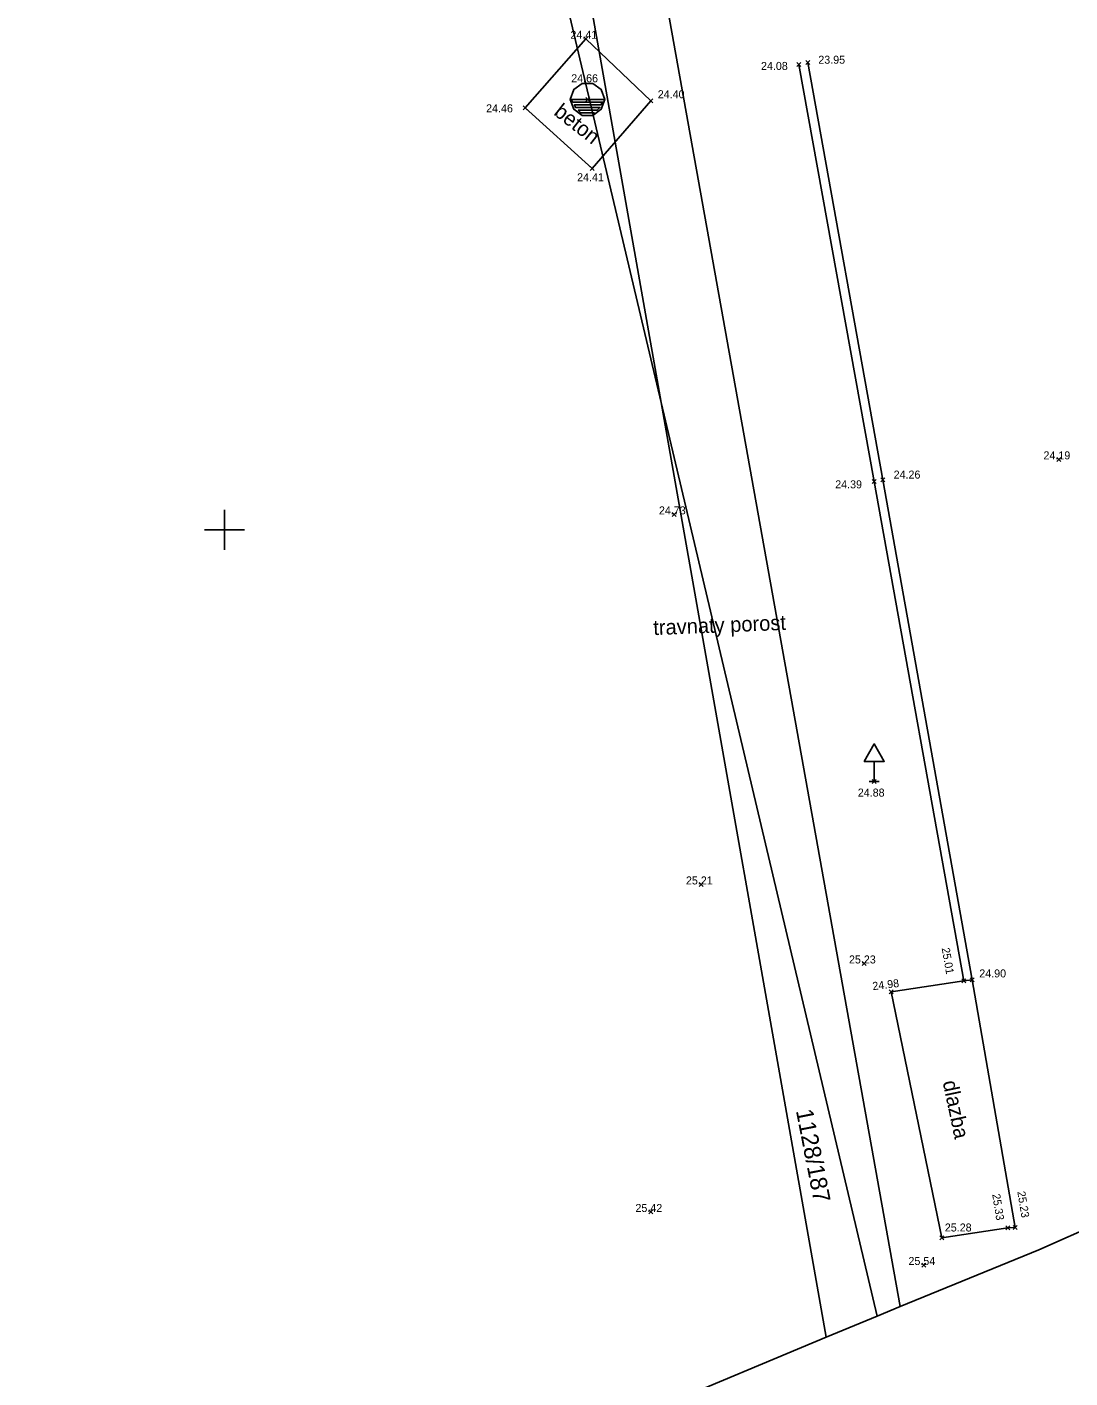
# Model space of a CAD drawing. Extents: x -772300 to -772183, y -1034101 to -1034019.
# Drawn here: x -772278.95 to -772258.1, y -1034066.96 to -1034039.94 of the extents above; entities that cross this region are included whole.
import ezdxf

# ---------------------------------------------------------------- set-up
doc = ezdxf.new("R2010")
doc.units = 0
for name, color, linetype in [('body', 7, 'Continuous'), ('dopravni_znacky', 7, 'Continuous'), ('elektricke_vedeni', 7, 'Continuous'), ('KM_hranice', 7, 'Continuous'), ('KM_popis', 7, 'Continuous'), ('mistni_popis', 7, 'Continuous'), ('oddeleni_ploch', 7, 'Continuous'), ('souradnicova_sit', 7, 'Continuous'), ('vyskove_koty', 7, 'Continuous')]:
    doc.layers.add(name, color=color, linetype=linetype)

msp = doc.modelspace()

# ---------------------------------------------------------------- linework, layer by layer
at = {"layer": 'body'}
for p, q in [((-772267.74, -1034040.22), (-772267.82, -1034040.14)), ((-772267.82, -1034040.22), (-772267.74, -1034040.14)), ((-772263.48, -1034040.73), (-772263.56, -1034040.65)), ((-772263.56, -1034040.73), (-772263.48, -1034040.65)), ((-772263.3, -1034040.69), (-772263.38, -1034040.61)), ((-772263.38, -1034040.69), (-772263.3, -1034040.61)), ((-772268.95, -1034041.6), (-772269.03, -1034041.52)), ((-772269.03, -1034041.6), (-772268.95, -1034041.52)), ((-772267.7, -1034041.43), (-772267.78, -1034041.35)), ((-772267.78, -1034041.43), (-772267.7, -1034041.35)), ((-772266.44, -1034041.46), (-772266.52, -1034041.38)), ((-772266.52, -1034041.46), (-772266.44, -1034041.38)), ((-772267.61, -1034042.81), (-772267.69, -1034042.73)), ((-772267.69, -1034042.81), (-772267.61, -1034042.73)), ((-772258.28, -1034048.63), (-772258.36, -1034048.55)), ((-772258.36, -1034048.63), (-772258.28, -1034048.55)), ((-772261.97, -1034049.07), (-772262.05, -1034048.99)), ((-772262.05, -1034049.07), (-772261.97, -1034048.99)), ((-772261.8, -1034049.04), (-772261.88, -1034048.96)), ((-772261.88, -1034049.04), (-772261.8, -1034048.96)), ((-772265.97, -1034049.73), (-772266.05, -1034049.65)), ((-772266.05, -1034049.73), (-772265.97, -1034049.65)), ((-772261.97, -1034055.07), (-772262.05, -1034054.99)), ((-772262.05, -1034055.07), (-772261.97, -1034054.99)), ((-772265.43, -1034057.13), (-772265.51, -1034057.05)), ((-772265.51, -1034057.13), (-772265.43, -1034057.05)), ((-772262.17, -1034058.71), (-772262.25, -1034058.63)), ((-772262.25, -1034058.71), (-772262.17, -1034058.63)), ((-772260.18, -1034059.06), (-772260.26, -1034058.98)), ((-772260.26, -1034059.06), (-772260.18, -1034058.98)), ((-772260.01, -1034059.04), (-772260.09, -1034058.96)), ((-772260.09, -1034059.04), (-772260.01, -1034058.96)), ((-772261.63, -1034059.28), (-772261.71, -1034059.2)), ((-772261.71, -1034059.28), (-772261.63, -1034059.2)), ((-772266.44, -1034063.68), (-772266.52, -1034063.6)), ((-772266.52, -1034063.68), (-772266.44, -1034063.6)), ((-772259.3, -1034064), (-772259.38, -1034063.92)), ((-772259.38, -1034064), (-772259.3, -1034063.92)), ((-772259.15, -1034063.99), (-772259.23, -1034063.91)), ((-772259.23, -1034063.99), (-772259.15, -1034063.91)), ((-772260.62, -1034064.2), (-772260.7, -1034064.12)), ((-772260.7, -1034064.2), (-772260.62, -1034064.12)), ((-772260.98, -1034064.74), (-772261.06, -1034064.66)), ((-772261.06, -1034064.74), (-772260.98, -1034064.66))]:
    msp.add_line(p, q, dxfattribs=at)
at = {"layer": 'dopravni_znacky'}
msp.add_line((-772262.11, -1034055.03), (-772261.91, -1034055.03), dxfattribs=at)
msp.add_lwpolyline([(-772262.01, -1034055.03), (-772262.01, -1034054.63), (-772261.81, -1034054.63), (-772262.01, -1034054.28), (-772262.21, -1034054.63), (-772262.01, -1034054.63)], dxfattribs=at)
at = {"layer": 'elektricke_vedeni'}
msp.add_lwpolyline([(-772267.4, -1034041.39), (-772267.468, -1034041.587), (-772267.638, -1034041.71), (-772267.849, -1034041.71), (-772268.019, -1034041.587), (-772268.087, -1034041.39), (-772268.019, -1034041.193), (-772267.849, -1034041.07), (-772267.638, -1034041.07), (-772267.468, -1034041.193), (-772267.4, -1034041.39), (-772268.08, -1034041.39), (-772268.039, -1034041.444), (-772267.441, -1034041.444), (-772267.475, -1034041.499), (-772268.005, -1034041.499), (-772267.985, -1034041.553), (-772267.495, -1034041.553), (-772267.55, -1034041.608), (-772267.93, -1034041.608), (-772267.876, -1034041.662), (-772267.604, -1034041.662)], dxfattribs=at)
at = {"layer": 'KM_hranice'}
for p, q in [((-772273.024, -1034018.905), (-772266.27, -1034047.45)), ((-772271.316, -1034018.905), (-772266.27, -1034047.45)), ((-772261.49, -1034065.53), (-772269.849, -1034018.905)), ((-772266.27, -1034047.45), (-772262.97, -1034066.14)), ((-772266.27, -1034047.45), (-772261.95, -1034065.72)), ((-772250.49, -1034060.71), (-772258.72, -1034064.4)), ((-772258.72, -1034064.4), (-772261.49, -1034065.53)), ((-772261.49, -1034065.53), (-772261.95, -1034065.72)), ((-772261.95, -1034065.72), (-772262.97, -1034066.14)), ((-772262.97, -1034066.14), (-772287.27, -1034076.31))]:
    msp.add_line(p, q, dxfattribs=at)
at = {"layer": 'oddeleni_ploch'}
msp.add_line((-772260.05, -1034059), (-772259.19, -1034063.95), dxfattribs=at)
msp.add_lwpolyline([(-772266.48, -1034041.42), (-772267.78, -1034040.18), (-772268.99, -1034041.56), (-772267.65, -1034042.77)], close=True, dxfattribs=at)
for points in [[(-772263.52, -1034040.69), (-772262.01, -1034049.03), (-772260.22, -1034059.02), (-772261.67, -1034059.24), (-772260.66, -1034064.16), (-772259.34, -1034063.96), (-772259.19, -1034063.95)], [(-772263.34, -1034040.65), (-772261.84, -1034049), (-772260.05, -1034059), (-772260.22, -1034059.02)]]:
    msp.add_lwpolyline(points, dxfattribs=at)
at = {"layer": 'souradnicova_sit'}
for p, q in [((-772275, -1034049.6), (-772275, -1034050.4)), ((-772275.4, -1034050), (-772274.6, -1034050))]:
    msp.add_line(p, q, dxfattribs=at)

# ---------------------------------------------------------------- texts
at = {"layer": 'KM_popis'}
msp.add_text('1128/187', height=0.34, rotation=281.0931, dxfattribs=at).set_placement((-772263.577, -1034061.614))
at = {"layer": 'mistni_popis'}
for s, rotation, p in [('beton', 321.945, (-772268.437, -1034041.686)), ('travnaty porost', 2.2918, (-772266.422, -1034052.105)), ('dlazba', 281.8952, (-772260.642, -1034061.04))]:
    msp.add_text(s, height=0.3, rotation=rotation, dxfattribs=at).set_placement(p)
at = {"layer": 'vyskove_koty'}
for s, p in [('24.41', (-772268.085, -1034040.18)), ('24.08', (-772264.274, -1034040.802)), ('23.95', (-772263.128, -1034040.678)), ('24.66', (-772268.069, -1034041.049)), ('24.40', (-772266.338, -1034041.368)), ('24.46', (-772269.771, -1034041.65)), ('24.41', (-772267.951, -1034043.028)), ('24.19', (-772258.625, -1034048.59)), ('24.26', (-772261.622, -1034048.974)), ('24.39', (-772262.79, -1034049.169)), ('24.73', (-772266.315, -1034049.69)), ('24.88', (-772262.338, -1034055.333)), ('25.21', (-772265.775, -1034057.09)), ('25.23', (-772262.515, -1034058.67)), ('24.90', (-772259.909, -1034058.949)), ('25.42', (-772266.785, -1034063.64)), ('25.28', (-772260.598, -1034064.03)), ('25.54', (-772261.325, -1034064.7))]:
    msp.add_text(s, height=0.16, dxfattribs=at).set_placement(p)
for s, rotation, p in [('25.01', 279.8326, (-772260.661, -1034058.367)), ('24.98', 6.9328, (-772262.036, -1034059.204)), ('25.33', 279.0304, (-772259.651, -1034063.288)), ('25.23', 279.3169, (-772259.149, -1034063.237))]:
    msp.add_text(s, height=0.16, rotation=rotation, dxfattribs=at).set_placement(p)

doc.saveas('drawing.dxf')
